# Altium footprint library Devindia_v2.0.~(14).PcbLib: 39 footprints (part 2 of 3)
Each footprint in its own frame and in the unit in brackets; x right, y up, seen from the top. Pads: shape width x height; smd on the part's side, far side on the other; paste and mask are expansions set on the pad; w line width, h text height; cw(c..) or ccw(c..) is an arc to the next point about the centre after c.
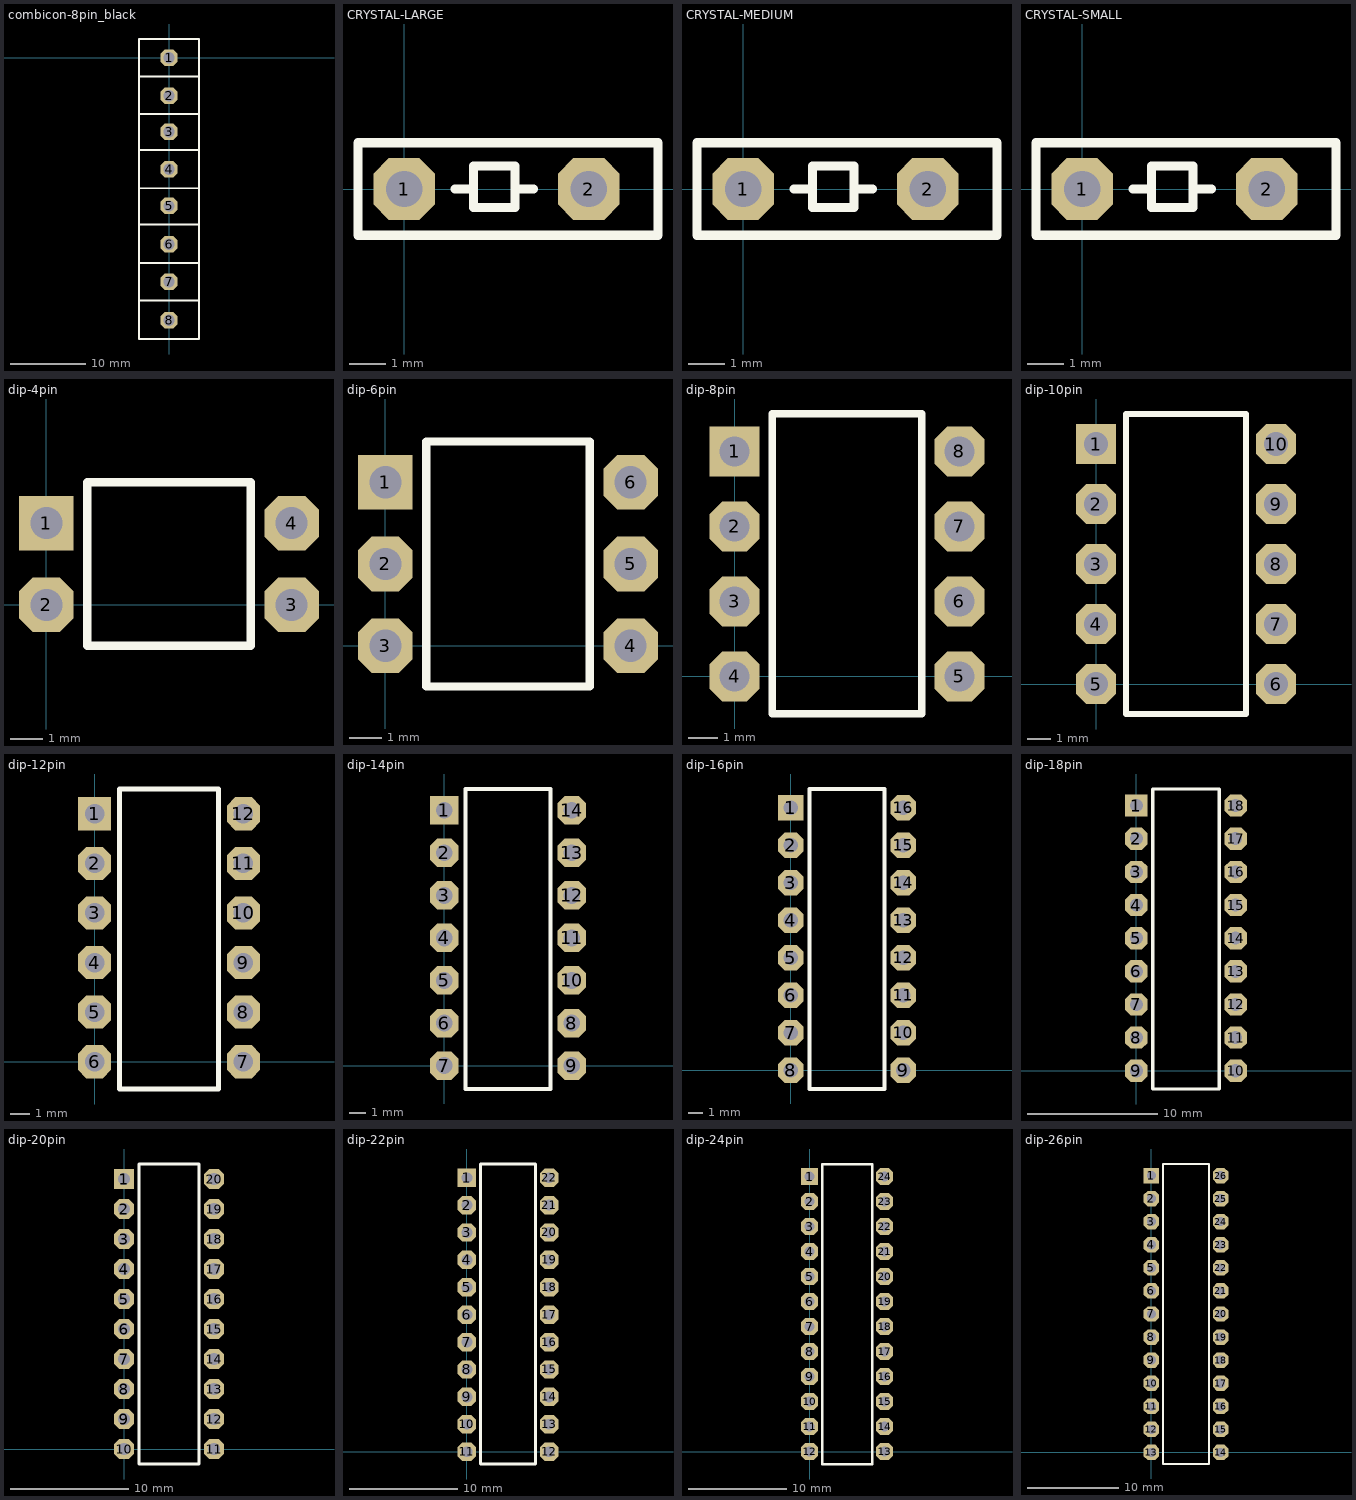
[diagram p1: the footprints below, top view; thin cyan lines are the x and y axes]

## combicon-8pin_black [mm]
pads (8):
  oct 2.2x2.2 hole 1.5: 1(0,0) 2(0,-5.08) 3(0,-9.85) 4(0,-14.875) 5(0,-19.75) 6(0,-24.875) 7(0,-29.875) 8(0,-35)
Top Overlay:
  lines w0.254: -4,-32.375 3.95,-32.375 4,-32.325 4,-27.375 ; -4,-22.25 4,-22.25 ; -4,-17.4 4,-17.4 ; -4,-12.325 4,-12.325 ; -4,-2.5 4,-2.5 ; -3.925,-27.375 4,-27.375 ; -4,-7.5 4,-7.5 ; -4,-7.5 -4,2.5 4,2.5 4,-7.5 ; -4,-7.5 -4,-27.3 -4,-37.5 4,-37.5 4,-27.375 ; 4,-27.375 4,-7.5
3D body: height 8.5, standoff 0, extent -3.937,-2.413 3.937,2.413
3D body: height 8.5, standoff 0, extent -3.937,-7.493 3.937,-2.413
3D body: height 12.4, standoff 8.5, extent -2.679,-37.537 4,2.413
3D body: height 12.9, standoff 12.4, extent -1.905,-6.731 1.88,-2.939
3D body: height 12.9, standoff 12.4, extent -1.778,-1.905 2.007,1.887
3D body: height 8.5, standoff 0, extent -3.937,-17.399 3.937,-12.319
3D body: height 8.5, standoff 0, extent -3.937,-12.319 3.937,-7.493
3D body: height 8.5, standoff 0, extent -3.937,-27.305 3.937,-22.225
3D body: height 8.5, standoff 0, extent -3.937,-22.225 3.937,-17.399
3D body: height 12.9, standoff 12.4, extent -1.853,-11.78 1.932,-7.987
3D body: height 12.9, standoff 12.4, extent -1.828,-16.755 1.957,-12.963
3D body: height 12.9, standoff 12.4, extent -1.803,-21.73 1.982,-17.938
3D body: height 12.9, standoff 12.4, extent -1.803,-26.755 1.982,-22.963
3D body: height 8.5, standoff 0, extent -3.937,-32.33 3.937,-27.25
3D body: height 8.5, standoff 0, extent -3.937,-37.405 3.937,-32.325
3D body: height 12.9, standoff 12.4, extent -1.803,-31.755 1.982,-27.963
3D body: height 12.9, standoff 12.4, extent -1.803,-36.88 1.982,-33.088

## CRYSTAL-LARGE [mm]
pads (2):
  oct 1.7x1.7 hole 1: 1(0,0) 2(5.08,0)
Top Overlay:
  lines w0.254: 1.397,0 1.905,0 ; 3.048,0 3.556,0 ; -1.27,-1.27 -1.27,1.27 6.985,1.27 6.985,-1.27 -1.27,-1.27 ; 1.905,-0.508 1.905,0.635 3.048,0.635 3.048,-0.508 1.905,-0.508
3D body: height 0.3, standoff 0, extent 3.483,-2.191 7.874,2.191
3D body: height 0.3, standoff 0, extent -2.069,-2.224 2.323,2.159
3D body: height 0.3, standoff 0, extent 0,-2.25 6.1,2.159
3D body: height 13.15, standoff 0.3, extent -1.715,-1.743 1.778,1.743
3D body: height 13.15, standoff 0.3, extent 3.873,-1.743 7.366,1.743
3D body: height 13.1, standoff 0.3, extent -0.254,-1.778 5.334,1.778

## CRYSTAL-MEDIUM [mm]
pads (2):
  oct 1.7x1.7 hole 1: 1(0,0) 2(5.08,0)
Top Overlay:
  lines w0.254: 1.397,0 1.905,0 ; 3.048,0 3.556,0 ; -1.27,-1.27 6.985,-1.27 6.985,1.27 -1.27,1.27 -1.27,-1.27 ; 1.905,-0.508 3.048,-0.508 3.048,0.635 1.905,0.635 1.905,-0.508
3D body: height 3.6, standoff 0.3, extent -0.254,-1.778 5.334,1.778
3D body: height 3.63, standoff 0.3, extent 3.873,-1.743 7.366,1.743
3D body: height 3.63, standoff 0.3, extent -1.715,-1.743 1.778,1.743
3D body: height 0.3, standoff 0, extent 0,-2.224 6.096,2.159
3D body: height 0.3, standoff 0, extent -2.069,-2.224 2.323,2.159
3D body: height 0.3, standoff 0, extent 3.483,-2.191 7.874,2.191

## CRYSTAL-SMALL [mm]
pads (2):
  oct 1.7x1.7 hole 1: 1(0,0) 2(5.08,0)
Top Overlay:
  lines w0.254: 1.397,0 1.905,0 ; 3.048,0 3.556,0 ; -1.27,-1.27 -1.27,1.27 6.985,1.27 6.985,-1.27 -1.27,-1.27 ; 1.905,-0.508 1.905,0.635 3.048,0.635 3.048,-0.508 1.905,-0.508
3D body: height 0.3, standoff 0, extent 3.429,-2.225 7.821,2.158
3D body: height 0.3, standoff 0, extent -2.069,-2.224 2.323,2.159
3D body: height 0.3, standoff 0, extent 0,-2.225 6.1,2.159
3D body: height 3.63, standoff 0.3, extent -1.715,-1.743 1.778,1.743
3D body: height 3.63, standoff 0.3, extent 3.873,-1.743 7.366,1.743
3D body: height 3.6, standoff 0.3, extent -0.254,-1.75 5.6,1.75

## dip-4pin [mm]
pads (4):
  rect 1.7x1.7 hole 1: 1(0,2.54)
  oct 1.7x1.7 hole 1: 2(0,0) 3(7.62,0) 4(7.62,2.54)
Top Overlay:
  lines w0.254: 1.27,-1.27 1.27,3.81 6.35,3.81 6.35,-1.27 1.27,-1.27
3D body: height 2.5, standoff 2, extent 1.778,-1.27 5.842,3.81
3D body: height 2.51, standoff 2.5, extent 2.286,2.032 3.284,3.028
3D body: height 1.63, standoff 1.37, extent 5.715,2.159 7.62,2.921
3D body: height 1.5, standoff 0, extent 7.493,2.159 7.747,2.921
3D body: height 1.63, standoff 1.37, extent 7.494,2.159 7.746,2.921
3D body: height 1.63, standoff 1.37, extent 5.715,-0.381 7.62,0.381
3D body: height 1.5, standoff 0, extent 7.493,-0.381 7.747,0.381
3D body: height 1.63, standoff 1.37, extent 7.494,-0.381 7.746,0.381
3D body: height 1.63, standoff 1.37, extent 0,-0.381 1.905,0.381
3D body: height 1.5, standoff 0, extent -0.127,-0.381 0.127,0.381
3D body: height 1.63, standoff 1.37, extent -0.126,-0.381 0.126,0.381
3D body: height 1.63, standoff 1.37, extent -0.126,2.159 0.126,2.921
3D body: height 1.5, standoff 0, extent -0.127,2.159 0.127,2.921
3D body: height 1.63, standoff 1.37, extent 0,2.159 1.905,2.921
3D body: height 2, standoff 1.1, extent 1.27,-1.27 6.35,3.81

## dip-6pin [mm]
pads (6):
  rect 1.7x1.7 hole 1: 1(0,5.08)
  oct 1.7x1.7 hole 1: 2(0,2.54) 3(0,0) 4(7.62,0) 5(7.62,2.54) 6(7.62,5.08)
Top Overlay:
  lines w0.254: 1.27,-1.27 6.35,-1.27 6.35,6.35 1.27,6.35 1.27,-1.27
3D body: height 1.63, standoff 1.37, extent -0.127,2.159 1.778,2.921
3D body: height 1.63, standoff 1.37, extent -0.127,4.699 1.778,5.461
3D body: height 1.63, standoff 1.37, extent -0.127,-0.381 1.778,0.381
3D body: height 1.63, standoff 1.37, extent 5.842,-0.381 7.747,0.381
3D body: height 1.63, standoff 1.37, extent 5.842,2.159 7.747,2.921
3D body: height 1.63, standoff 1.37, extent 5.842,4.699 7.747,5.461
3D body: height 1.63, standoff 1.37, extent -0.126,4.699 0.126,5.461
3D body: height 1.5, standoff 0, extent -0.127,4.699 0.127,5.461
3D body: height 1.63, standoff 1.37, extent -0.126,2.159 0.126,2.921
3D body: height 1.5, standoff 0, extent -0.127,2.159 0.127,2.921
3D body: height 1.63, standoff 1.37, extent -0.126,-0.381 0.126,0.381
3D body: height 1.5, standoff 0, extent -0.127,-0.381 0.127,0.381
3D body: height 1.63, standoff 1.37, extent 7.494,-0.381 7.746,0.381
3D body: height 1.5, standoff 0, extent 7.493,-0.381 7.747,0.381
3D body: height 1.63, standoff 1.37, extent 7.494,2.159 7.746,2.921
3D body: height 1.5, standoff 0, extent 7.493,2.159 7.747,2.921
3D body: height 1.63, standoff 1.37, extent 7.494,4.699 7.746,5.461
3D body: height 1.5, standoff 0, extent 7.493,4.699 7.747,5.461
3D body: height 2, standoff 1.1, extent 1.27,-1.27 6.35,6.35
3D body: height 2.51, standoff 2.5, extent 2.041,4.592 3.039,5.588
3D body: height 2.5, standoff 2, extent 1.778,-1.27 5.842,6.35

## dip-8pin [mm]
pads (8):
  rect 1.7x1.7 hole 1: 1(0,7.62)
  oct 1.7x1.7 hole 1: 2(0,5.08) 3(0,2.54) 4(0,0) 5(7.62,0) 6(7.62,2.54) 7(7.62,5.08) 8(7.62,7.62)
Top Overlay:
  lines w0.254: 1.27,-1.27 6.35,-1.27 6.35,8.89 1.27,8.89 1.27,-1.27
3D body: height 1.63, standoff 1.37, extent -0.127,4.699 1.778,5.461
3D body: height 1.63, standoff 1.37, extent -0.127,7.239 1.778,8.001
3D body: height 1.63, standoff 1.37, extent -0.127,2.159 1.778,2.921
3D body: height 1.63, standoff 1.37, extent -0.127,-0.381 1.778,0.381
3D body: height 1.63, standoff 1.37, extent 5.842,-0.381 7.747,0.381
3D body: height 1.63, standoff 1.37, extent 5.842,2.159 7.747,2.921
3D body: height 1.63, standoff 1.37, extent 5.842,4.699 7.747,5.461
3D body: height 1.63, standoff 1.37, extent 5.842,7.239 7.747,8.001
3D body: height 1.63, standoff 1.37, extent -0.126,7.239 0.126,8.001
3D body: height 1.5, standoff 0, extent -0.127,7.239 0.127,8.001
3D body: height 1.63, standoff 1.37, extent -0.126,4.699 0.126,5.461
3D body: height 1.5, standoff 0, extent -0.127,4.699 0.127,5.461
3D body: height 1.63, standoff 1.37, extent -0.126,2.159 0.126,2.921
3D body: height 1.5, standoff 0, extent -0.127,2.159 0.127,2.921
3D body: height 1.63, standoff 1.37, extent -0.126,-0.381 0.126,0.381
3D body: height 1.5, standoff 0, extent -0.127,-0.381 0.127,0.381
3D body: height 1.63, standoff 1.37, extent 7.494,-0.381 7.746,0.381
3D body: height 1.5, standoff 0, extent 7.493,-0.381 7.747,0.381
3D body: height 1.63, standoff 1.37, extent 7.494,2.159 7.746,2.921
3D body: height 1.5, standoff 0, extent 7.493,2.159 7.747,2.921
3D body: height 1.63, standoff 1.37, extent 7.494,4.699 7.746,5.461
3D body: height 1.5, standoff 0, extent 7.493,4.699 7.747,5.461
3D body: height 1.63, standoff 1.37, extent 7.494,7.239 7.746,8.001
3D body: height 1.5, standoff 0, extent 7.493,7.239 7.747,8.001
3D body: height 2, standoff 1.1, extent 1.27,-1.27 6.35,8.89
3D body: height 2.51, standoff 2.5, extent 2.041,7.132 3.039,8.128
3D body: height 2.5, standoff 2, extent 1.778,-1.27 5.842,8.89

## dip-10pin [mm]
pads (10):
  rect 1.7x1.7 hole 1: 1(0,10.16)
  oct 1.7x1.7 hole 1: 2(0,7.62) 3(0,5.08) 4(0,2.54) 5(0,0) 6(7.62,0) 7(7.62,2.54) 8(7.62,5.08) 9(7.62,7.62) 10(7.62,10.16)
Top Overlay:
  lines w0.254: 1.27,-1.27 6.35,-1.27 6.35,11.43 1.27,11.43 1.27,-1.27
3D body: height 1.5, standoff 0, extent 7.493,4.699 7.747,5.461
3D body: height 1.63, standoff 1.37, extent 7.494,4.699 7.746,5.461
3D body: height 1.63, standoff 1.37, extent 5.842,4.699 7.747,5.461
3D body: height 1.63, standoff 1.37, extent -0.127,7.239 1.778,8.001
3D body: height 1.63, standoff 1.37, extent -0.127,9.779 1.778,10.541
3D body: height 1.63, standoff 1.37, extent -0.127,4.699 1.778,5.461
3D body: height 1.63, standoff 1.37, extent -0.127,2.159 1.778,2.921
3D body: height 1.63, standoff 1.37, extent -0.127,-0.381 1.778,0.381
3D body: height 1.63, standoff 1.37, extent 5.842,-0.381 7.747,0.381
3D body: height 1.63, standoff 1.37, extent 5.842,2.159 7.747,2.921
3D body: height 1.63, standoff 1.37, extent 5.842,9.779 7.747,10.541
3D body: height 1.63, standoff 1.37, extent -0.126,9.779 0.126,10.541
3D body: height 1.5, standoff 0, extent -0.127,9.779 0.127,10.541
3D body: height 1.63, standoff 1.37, extent -0.126,7.239 0.126,8.001
3D body: height 1.5, standoff 0, extent -0.127,7.239 0.127,8.001
3D body: height 1.63, standoff 1.37, extent -0.126,4.699 0.126,5.461
3D body: height 1.5, standoff 0, extent -0.127,4.699 0.127,5.461
3D body: height 1.63, standoff 1.37, extent -0.126,2.159 0.126,2.921
3D body: height 1.5, standoff 0, extent -0.127,2.159 0.127,2.921
3D body: height 1.63, standoff 1.37, extent -0.126,-0.381 0.126,0.381
3D body: height 1.5, standoff 0, extent -0.127,-0.381 0.127,0.381
3D body: height 1.63, standoff 1.37, extent 7.494,-0.381 7.746,0.381
3D body: height 1.5, standoff 0, extent 7.493,-0.381 7.747,0.381
3D body: height 1.63, standoff 1.37, extent 7.494,2.159 7.746,2.921
3D body: height 1.5, standoff 0, extent 7.493,2.159 7.747,2.921
3D body: height 1.63, standoff 1.37, extent 7.494,9.779 7.746,10.541
3D body: height 1.5, standoff 0, extent 7.493,9.779 7.747,10.541
3D body: height 2, standoff 1.1, extent 1.27,-1.27 6.35,11.43
3D body: height 2.51, standoff 2.5, extent 2.041,9.672 3.039,10.668
3D body: height 2.5, standoff 2, extent 1.778,-1.27 5.842,11.43
3D body: height 1.63, standoff 1.37, extent 5.842,7.239 7.747,8.001
3D body: height 1.63, standoff 1.37, extent 7.494,7.239 7.746,8.001
3D body: height 1.5, standoff 0, extent 7.493,7.239 7.747,8.001

## dip-12pin [mm]
pads (12):
  rect 1.7x1.7 hole 1: 1(0,12.7)
  oct 1.7x1.7 hole 1: 2(0,10.16) 3(0,7.62) 4(0,5.08) 5(0,2.54) 6(0,0) 7(7.62,0) 8(7.62,2.54) 9(7.62,5.08) 10(7.62,7.62) 11(7.62,10.16) 12(7.62,12.7)
Top Overlay:
  lines w0.254: 1.27,-1.397 1.27,13.97 6.35,13.97 6.35,-1.397 1.27,-1.397
3D body: height 1.5, standoff 0, extent 7.493,4.699 7.747,5.461
3D body: height 1.63, standoff 1.37, extent 7.494,4.699 7.746,5.461
3D body: height 1.63, standoff 1.37, extent 5.842,4.699 7.747,5.461
3D body: height 2.5, standoff 2, extent 1.778,-1.27 5.842,13.97
3D body: height 2.51, standoff 2.5, extent 2.041,12.212 3.039,13.208
3D body: height 2, standoff 1.1, extent 1.27,-1.397 6.35,13.97
3D body: height 1.5, standoff 0, extent 7.493,12.319 7.747,13.081
3D body: height 1.63, standoff 1.37, extent 7.494,12.319 7.746,13.081
3D body: height 1.5, standoff 0, extent 7.493,9.779 7.747,10.541
3D body: height 1.63, standoff 1.37, extent 7.494,9.779 7.746,10.541
3D body: height 1.5, standoff 0, extent 7.493,7.239 7.747,8.001
3D body: height 1.63, standoff 1.37, extent 7.494,7.239 7.746,8.001
3D body: height 1.5, standoff 0, extent 7.493,2.159 7.747,2.921
3D body: height 1.63, standoff 1.37, extent 7.494,2.159 7.746,2.921
3D body: height 1.5, standoff 0, extent 7.493,-0.381 7.747,0.381
3D body: height 1.63, standoff 1.37, extent 7.494,-0.381 7.746,0.381
3D body: height 1.5, standoff 0, extent -0.127,-0.381 0.127,0.381
3D body: height 1.63, standoff 1.37, extent -0.126,-0.381 0.126,0.381
3D body: height 1.5, standoff 0, extent -0.127,2.159 0.127,2.921
3D body: height 1.63, standoff 1.37, extent -0.126,2.159 0.126,2.921
3D body: height 1.5, standoff 0, extent -0.127,4.699 0.127,5.461
3D body: height 1.63, standoff 1.37, extent -0.126,4.699 0.126,5.461
3D body: height 1.5, standoff 0, extent -0.127,7.239 0.127,8.001
3D body: height 1.63, standoff 1.37, extent -0.126,7.239 0.126,8.001
3D body: height 1.5, standoff 0, extent -0.127,9.779 0.127,10.541
3D body: height 1.63, standoff 1.37, extent -0.126,9.779 0.126,10.541
3D body: height 1.5, standoff 0, extent -0.127,12.319 0.127,13.081
3D body: height 1.63, standoff 1.37, extent -0.126,12.319 0.126,13.081
3D body: height 1.63, standoff 1.37, extent 5.842,12.319 7.747,13.081
3D body: height 1.63, standoff 1.37, extent 5.842,9.779 7.747,10.541
3D body: height 1.63, standoff 1.37, extent 5.842,7.239 7.747,8.001
3D body: height 1.63, standoff 1.37, extent 5.842,2.159 7.747,2.921
3D body: height 1.63, standoff 1.37, extent 5.842,-0.381 7.747,0.381
3D body: height 1.63, standoff 1.37, extent -0.127,-0.381 1.778,0.381
3D body: height 1.63, standoff 1.37, extent -0.127,2.159 1.778,2.921
3D body: height 1.63, standoff 1.37, extent -0.127,4.699 1.778,5.461
3D body: height 1.63, standoff 1.37, extent -0.127,7.239 1.778,8.001
3D body: height 1.63, standoff 1.37, extent -0.127,12.319 1.778,13.081
3D body: height 1.63, standoff 1.37, extent -0.127,9.779 1.778,10.541

## dip-14pin [mm]
pads (14):
  rect 1.7x1.7 hole 1: 1(0,15.24)
  oct 1.7x1.7 hole 1: 2(0,12.7) 3(0,10.16) 4(0,7.62) 5(0,5.08) 6(0,2.54) 7(0,0) 8(7.62,2.54) 9(7.62,0) 10(7.62,5.08) 11(7.62,7.62) 12(7.62,10.16) 13(7.62,12.7) 14(7.62,15.24)
Top Overlay:
  lines w0.254: 1.27,-1.397 6.35,-1.397 6.35,16.51 1.27,16.51 1.27,-1.397
3D body: height 1.5, standoff 0, extent 7.493,2.159 7.747,2.921
3D body: height 1.63, standoff 1.37, extent 7.494,2.159 7.746,2.921
3D body: height 1.63, standoff 1.37, extent 5.842,2.159 7.747,2.921
3D body: height 1.63, standoff 1.37, extent 7.621,14.859 7.873,15.621
3D body: height 1.5, standoff 0, extent 7.62,14.859 7.874,15.621
3D body: height 1.63, standoff 1.37, extent 5.842,14.859 7.747,15.621
3D body: height 1.63, standoff 1.37, extent 5.842,12.319 7.747,13.081
3D body: height 1.5, standoff 0, extent 7.62,12.319 7.874,13.081
3D body: height 1.63, standoff 1.37, extent 7.621,12.319 7.873,13.081
3D body: height 1.63, standoff 1.37, extent -0.127,12.319 1.778,13.081
3D body: height 1.63, standoff 1.37, extent -0.127,14.859 1.778,15.621
3D body: height 1.63, standoff 1.37, extent -0.127,9.779 1.778,10.541
3D body: height 1.63, standoff 1.37, extent -0.127,7.239 1.778,8.001
3D body: height 1.63, standoff 1.37, extent -0.127,4.699 1.778,5.461
3D body: height 1.63, standoff 1.37, extent -0.127,2.159 1.778,2.921
3D body: height 1.63, standoff 1.37, extent -0.127,-0.381 1.778,0.381
3D body: height 1.63, standoff 1.37, extent 5.842,-0.381 7.747,0.381
3D body: height 1.63, standoff 1.37, extent 5.842,4.699 7.747,5.461
3D body: height 1.63, standoff 1.37, extent 5.842,7.239 7.747,8.001
3D body: height 1.63, standoff 1.37, extent 5.842,9.779 7.747,10.541
3D body: height 1.63, standoff 1.37, extent -0.126,14.859 0.126,15.621
3D body: height 1.5, standoff 0, extent -0.127,14.859 0.127,15.621
3D body: height 1.63, standoff 1.37, extent -0.126,12.319 0.126,13.081
3D body: height 1.5, standoff 0, extent -0.127,12.319 0.127,13.081
3D body: height 1.63, standoff 1.37, extent -0.126,9.779 0.126,10.541
3D body: height 1.5, standoff 0, extent -0.127,9.779 0.127,10.541
3D body: height 1.63, standoff 1.37, extent -0.126,7.239 0.126,8.001
3D body: height 1.5, standoff 0, extent -0.127,7.239 0.127,8.001
3D body: height 1.63, standoff 1.37, extent -0.126,4.699 0.126,5.461
3D body: height 1.5, standoff 0, extent -0.127,4.699 0.127,5.461
3D body: height 1.63, standoff 1.37, extent -0.126,2.159 0.126,2.921
3D body: height 1.5, standoff 0, extent -0.127,2.159 0.127,2.921
3D body: height 1.63, standoff 1.37, extent -0.126,-0.381 0.126,0.381
3D body: height 1.5, standoff 0, extent -0.127,-0.381 0.127,0.381
3D body: height 1.63, standoff 1.37, extent 7.494,-0.381 7.746,0.381
3D body: height 1.5, standoff 0, extent 7.493,-0.381 7.747,0.381
3D body: height 1.63, standoff 1.37, extent 7.494,4.699 7.746,5.461
3D body: height 1.5, standoff 0, extent 7.493,4.699 7.747,5.461
3D body: height 1.63, standoff 1.37, extent 7.494,7.239 7.746,8.001
3D body: height 1.5, standoff 0, extent 7.493,7.239 7.747,8.001
3D body: height 1.63, standoff 1.37, extent 7.494,9.779 7.746,10.541
3D body: height 1.5, standoff 0, extent 7.493,9.779 7.747,10.541
3D body: height 2, standoff 1.1, extent 1.27,-1.27 6.35,16.51
3D body: height 2.51, standoff 2.5, extent 2.041,14.752 3.039,15.748
3D body: height 2.5, standoff 2, extent 1.778,-1.397 5.842,16.51

## dip-16pin [mm]
pads (16):
  rect 1.7x1.7 hole 1: 1(0,17.78)
  oct 1.7x1.7 hole 1: 2(0,15.24) 3(0,12.7) 4(0,10.16) 5(0,7.62) 6(0,5.08) 7(0,2.54) 8(0,0) 9(7.62,0) 10(7.62,2.54) 11(7.62,5.08) 12(7.62,7.62) 13(7.62,10.16) 14(7.62,12.7) 15(7.62,15.24) 16(7.62,17.78)
Top Overlay:
  lines w0.254: 1.27,-1.27 1.27,19.05 6.35,19.05 6.35,-1.27 1.27,-1.27
3D body: height 1.63, standoff 1.37, extent 7.621,12.319 7.873,13.081
3D body: height 1.5, standoff 0, extent 7.62,12.319 7.874,13.081
3D body: height 1.63, standoff 1.37, extent 5.842,12.319 7.747,13.081
3D body: height 2.5, standoff 2, extent 1.778,-1.27 5.842,19.05
3D body: height 2.51, standoff 2.5, extent 2.041,17.292 3.039,18.288
3D body: height 1.5, standoff 0, extent 7.493,17.399 7.747,18.161
3D body: height 1.63, standoff 1.37, extent 7.494,17.399 7.746,18.161
3D body: height 2, standoff 1.1, extent 1.27,-1.27 6.35,19.05
3D body: height 1.5, standoff 0, extent 7.493,7.239 7.747,8.001
3D body: height 1.63, standoff 1.37, extent 7.494,7.239 7.746,8.001
3D body: height 1.5, standoff 0, extent 7.493,4.699 7.747,5.461
3D body: height 1.63, standoff 1.37, extent 7.494,4.699 7.746,5.461
3D body: height 1.5, standoff 0, extent 7.493,2.159 7.747,2.921
3D body: height 1.63, standoff 1.37, extent 7.494,2.159 7.746,2.921
3D body: height 1.5, standoff 0, extent 7.493,-0.381 7.747,0.381
3D body: height 1.63, standoff 1.37, extent 7.494,-0.381 7.746,0.381
3D body: height 1.5, standoff 0, extent -0.127,-0.381 0.127,0.381
3D body: height 1.63, standoff 1.37, extent -0.126,-0.381 0.126,0.381
3D body: height 1.5, standoff 0, extent -0.127,2.159 0.127,2.921
3D body: height 1.63, standoff 1.37, extent -0.126,2.159 0.126,2.921
3D body: height 1.5, standoff 0, extent -0.127,4.699 0.127,5.461
3D body: height 1.63, standoff 1.37, extent -0.126,4.699 0.126,5.461
3D body: height 1.5, standoff 0, extent -0.127,7.239 0.127,8.001
3D body: height 1.63, standoff 1.37, extent -0.126,7.239 0.126,8.001
3D body: height 1.5, standoff 0, extent -0.127,9.779 0.127,10.541
3D body: height 1.63, standoff 1.37, extent -0.126,9.779 0.126,10.541
3D body: height 1.5, standoff 0, extent -0.127,12.319 0.127,13.081
3D body: height 1.63, standoff 1.37, extent -0.126,12.319 0.126,13.081
3D body: height 1.5, standoff 0, extent -0.127,14.859 0.127,15.621
3D body: height 1.63, standoff 1.37, extent -0.126,14.859 0.126,15.621
3D body: height 1.5, standoff 0, extent -0.127,17.399 0.127,18.161
3D body: height 1.63, standoff 1.37, extent -0.126,17.399 0.126,18.161
3D body: height 1.63, standoff 1.37, extent 5.842,7.239 7.747,8.001
3D body: height 1.63, standoff 1.37, extent 5.842,4.699 7.747,5.461
3D body: height 1.63, standoff 1.37, extent 5.842,2.159 7.747,2.921
3D body: height 1.63, standoff 1.37, extent 5.842,-0.381 7.747,0.381
3D body: height 1.63, standoff 1.37, extent -0.127,-0.381 1.778,0.381
3D body: height 1.63, standoff 1.37, extent -0.127,2.159 1.778,2.921
3D body: height 1.63, standoff 1.37, extent -0.127,4.699 1.778,5.461
3D body: height 1.63, standoff 1.37, extent -0.127,7.239 1.778,8.001
3D body: height 1.63, standoff 1.37, extent -0.127,9.779 1.778,10.541
3D body: height 1.63, standoff 1.37, extent -0.127,12.319 1.778,13.081
3D body: height 1.63, standoff 1.37, extent -0.127,17.399 1.778,18.161
3D body: height 1.63, standoff 1.37, extent -0.127,14.859 1.778,15.621
3D body: height 1.63, standoff 1.37, extent 7.621,9.779 7.873,10.541
3D body: height 1.5, standoff 0, extent 7.62,9.779 7.874,10.541
3D body: height 1.63, standoff 1.37, extent 5.842,9.779 7.747,10.541
3D body: height 1.63, standoff 1.37, extent 5.842,14.859 7.747,15.621
3D body: height 1.63, standoff 1.37, extent 5.842,17.399 7.747,18.161
3D body: height 1.5, standoff 0, extent 7.62,17.399 7.874,18.161
3D body: height 1.63, standoff 1.37, extent 7.621,17.399 7.873,18.161
3D body: height 1.5, standoff 0, extent 7.62,14.859 7.874,15.621
3D body: height 1.63, standoff 1.37, extent 7.621,14.859 7.873,15.621

## dip-18pin [mm]
pads (18):
  rect 1.7x1.7 hole 1: 1(0,20.32)
  oct 1.7x1.7 hole 1: 2(0,17.78) 3(0,15.24) 4(0,12.7) 5(0,10.16) 6(0,7.62) 7(0,5.08) 8(0,2.54) 9(0,0) 10(7.62,0) 11(7.62,2.54) 12(7.62,5.08) 13(7.62,7.62) 14(7.62,10.16) 15(7.62,12.7) 16(7.62,15.24) 17(7.62,17.78) 18(7.62,20.32)
Top Overlay:
  lines w0.254: 1.27,-1.397 6.35,-1.397 6.35,21.59 1.27,21.59 1.27,-1.397
3D body: height 1.63, standoff 1.37, extent 7.621,12.319 7.873,13.081
3D body: height 1.5, standoff 0, extent 7.62,12.319 7.874,13.081
3D body: height 1.63, standoff 1.37, extent 7.621,14.859 7.873,15.621
3D body: height 1.5, standoff 0, extent 7.62,14.859 7.874,15.621
3D body: height 1.63, standoff 1.37, extent 5.842,19.939 7.747,20.701
3D body: height 1.63, standoff 1.37, extent 5.842,17.399 7.747,18.161
3D body: height 1.63, standoff 1.37, extent 7.621,19.939 7.873,20.701
3D body: height 1.5, standoff 0, extent 7.62,19.939 7.874,20.701
3D body: height 1.63, standoff 1.37, extent 5.842,14.859 7.747,15.621
3D body: height 1.63, standoff 1.37, extent 7.621,17.399 7.873,18.161
3D body: height 1.5, standoff 0, extent 7.62,17.399 7.874,18.161
3D body: height 1.63, standoff 1.37, extent 5.842,12.319 7.747,13.081
3D body: height 1.63, standoff 1.37, extent 5.842,7.239 7.747,8.001
3D body: height 1.5, standoff 0, extent 7.62,7.239 7.874,8.001
3D body: height 1.63, standoff 1.37, extent 7.621,7.239 7.873,8.001
3D body: height 1.63, standoff 1.37, extent -0.127,17.399 1.778,18.161
3D body: height 1.63, standoff 1.37, extent -0.127,19.939 1.778,20.701
3D body: height 1.63, standoff 1.37, extent -0.127,14.859 1.778,15.621
3D body: height 1.63, standoff 1.37, extent -0.127,12.319 1.778,13.081
3D body: height 1.63, standoff 1.37, extent -0.127,9.779 1.778,10.541
3D body: height 1.63, standoff 1.37, extent -0.127,7.239 1.778,8.001
3D body: height 1.63, standoff 1.37, extent -0.127,4.699 1.778,5.461
3D body: height 1.63, standoff 1.37, extent -0.127,2.159 1.778,2.921
3D body: height 1.63, standoff 1.37, extent 5.842,-0.381 7.747,0.381
3D body: height 1.63, standoff 1.37, extent 5.842,2.159 7.747,2.921
3D body: height 1.63, standoff 1.37, extent 5.842,4.699 7.747,5.461
3D body: height 1.63, standoff 1.37, extent -0.126,19.939 0.126,20.701
3D body: height 1.5, standoff 0, extent -0.127,19.939 0.127,20.701
3D body: height 1.63, standoff 1.37, extent -0.126,17.399 0.126,18.161
3D body: height 1.5, standoff 0, extent -0.127,17.399 0.127,18.161
3D body: height 1.63, standoff 1.37, extent -0.126,14.859 0.126,15.621
3D body: height 1.5, standoff 0, extent -0.127,14.859 0.127,15.621
3D body: height 1.63, standoff 1.37, extent -0.126,12.319 0.126,13.081
3D body: height 1.5, standoff 0, extent -0.127,12.319 0.127,13.081
3D body: height 1.63, standoff 1.37, extent -0.126,9.779 0.126,10.541
3D body: height 1.5, standoff 0, extent -0.127,9.779 0.127,10.541
3D body: height 1.63, standoff 1.37, extent -0.126,7.239 0.126,8.001
3D body: height 1.5, standoff 0, extent -0.127,7.239 0.127,8.001
3D body: height 1.63, standoff 1.37, extent -0.126,4.699 0.126,5.461
3D body: height 1.5, standoff 0, extent -0.127,4.699 0.127,5.461
3D body: height 1.63, standoff 1.37, extent -0.126,2.159 0.126,2.921
3D body: height 1.5, standoff 0, extent -0.127,2.159 0.127,2.921
3D body: height 1.63, standoff 1.37, extent 7.494,-0.381 7.746,0.381
3D body: height 1.5, standoff 0, extent 7.493,-0.381 7.747,0.381
3D body: height 1.63, standoff 1.37, extent 7.494,2.159 7.746,2.921
3D body: height 1.5, standoff 0, extent 7.493,2.159 7.747,2.921
3D body: height 1.63, standoff 1.37, extent 7.494,4.699 7.746,5.461
3D body: height 1.5, standoff 0, extent 7.493,4.699 7.747,5.461
3D body: height 2, standoff 1.1, extent 1.27,-1.397 6.35,21.59
3D body: height 1.63, standoff 1.37, extent 7.494,14.859 7.746,15.621
3D body: height 1.5, standoff 0, extent 7.493,14.859 7.747,15.621
3D body: height 2.51, standoff 2.5, extent 2.041,19.832 3.039,20.828
3D body: height 2.5, standoff 2, extent 1.778,-1.397 5.842,21.59
3D body: height 1.63, standoff 1.37, extent -0.127,-0.381 1.778,0.381
3D body: height 1.63, standoff 1.37, extent -0.126,-0.381 0.126,0.381
3D body: height 1.5, standoff 0, extent -0.127,-0.381 0.127,0.381
3D body: height 1.63, standoff 1.37, extent 5.842,9.779 7.747,10.541
3D body: height 1.63, standoff 1.37, extent 7.494,9.779 7.746,10.541
3D body: height 1.5, standoff 0, extent 7.493,9.779 7.747,10.541

## dip-20pin [mm]
pads (20):
  rect 1.7x1.7 hole 1: 1(0,22.86)
  oct 1.7x1.7 hole 1: 2(0,20.32) 3(0,17.78) 4(0,15.24) 5(0,12.7) 6(0,10.16) 7(0,7.62) 8(0,5.08) 9(0,2.54) 10(0,0) 11(7.62,0) 12(7.62,2.54) 13(7.62,5.08) 14(7.62,7.62) 15(7.62,10.16) 16(7.62,12.7) 17(7.62,15.24) 18(7.62,17.78) 19(7.62,20.32) 20(7.62,22.86)
Top Overlay:
  lines w0.254: 1.27,-1.27 6.35,-1.27 6.35,24.13 1.27,24.13 1.27,-1.27
3D body: height 1.5, standoff 0, extent -0.127,4.699 0.127,5.461
3D body: height 1.63, standoff 1.37, extent -0.126,4.699 0.126,5.461
3D body: height 1.63, standoff 1.37, extent -0.127,4.699 1.778,5.461
3D body: height 1.5, standoff 0, extent 7.493,7.239 7.747,8.001
3D body: height 1.63, standoff 1.37, extent 7.494,7.239 7.746,8.001
3D body: height 1.63, standoff 1.37, extent 5.842,7.239 7.747,8.001
3D body: height 1.5, standoff 0, extent -0.127,2.159 0.127,2.921
3D body: height 1.63, standoff 1.37, extent -0.126,2.159 0.126,2.921
3D body: height 1.63, standoff 1.37, extent -0.127,2.159 1.778,2.921
3D body: height 1.63, standoff 1.37, extent 7.621,9.779 7.873,10.541
3D body: height 1.5, standoff 0, extent 7.62,9.779 7.874,10.541
3D body: height 1.63, standoff 1.37, extent 7.621,12.319 7.873,13.081
3D body: height 1.5, standoff 0, extent 7.62,12.319 7.874,13.081
3D body: height 1.63, standoff 1.37, extent 7.621,22.479 7.873,23.241
3D body: height 1.5, standoff 0, extent 7.62,22.479 7.874,23.241
3D body: height 1.63, standoff 1.37, extent 5.842,17.399 7.747,18.161
3D body: height 1.63, standoff 1.37, extent 7.621,19.939 7.873,20.701
3D body: height 1.5, standoff 0, extent 7.62,19.939 7.874,20.701
3D body: height 1.63, standoff 1.37, extent 5.842,14.859 7.747,15.621
3D body: height 1.63, standoff 1.37, extent 7.621,17.399 7.873,18.161
3D body: height 1.5, standoff 0, extent 7.62,17.399 7.874,18.161
3D body: height 1.63, standoff 1.37, extent 5.842,12.319 7.747,13.081
3D body: height 1.63, standoff 1.37, extent 7.621,14.859 7.873,15.621
3D body: height 1.5, standoff 0, extent 7.62,14.859 7.874,15.621
3D body: height 1.63, standoff 1.37, extent 5.842,9.779 7.747,10.541
3D body: height 1.63, standoff 1.37, extent 5.842,19.939 7.747,20.701
3D body: height 1.63, standoff 1.37, extent 5.842,22.479 7.747,23.241
3D body: height 1.63, standoff 1.37, extent 5.842,4.699 7.747,5.461
3D body: height 1.5, standoff 0, extent 7.62,4.699 7.874,5.461
3D body: height 1.63, standoff 1.37, extent 7.621,4.699 7.873,5.461
3D body: height 1.63, standoff 1.37, extent -0.127,19.939 1.778,20.701
3D body: height 1.63, standoff 1.37, extent -0.127,22.479 1.778,23.241
3D body: height 1.63, standoff 1.37, extent -0.127,17.399 1.778,18.161
3D body: height 1.63, standoff 1.37, extent -0.127,14.859 1.778,15.621
3D body: height 1.63, standoff 1.37, extent -0.127,12.319 1.778,13.081
3D body: height 1.63, standoff 1.37, extent -0.127,9.779 1.778,10.541
3D body: height 1.63, standoff 1.37, extent -0.127,7.239 1.778,8.001
3D body: height 1.63, standoff 1.37, extent -0.127,-0.381 1.778,0.381
3D body: height 1.63, standoff 1.37, extent 5.842,-0.381 7.747,0.381
3D body: height 1.63, standoff 1.37, extent 5.842,2.159 7.747,2.921
3D body: height 1.63, standoff 1.37, extent -0.126,22.479 0.126,23.241
3D body: height 1.5, standoff 0, extent -0.127,22.479 0.127,23.241
3D body: height 1.63, standoff 1.37, extent -0.126,19.939 0.126,20.701
3D body: height 1.5, standoff 0, extent -0.127,19.939 0.127,20.701
3D body: height 1.63, standoff 1.37, extent -0.126,17.399 0.126,18.161
3D body: height 1.5, standoff 0, extent -0.127,17.399 0.127,18.161
3D body: height 1.63, standoff 1.37, extent -0.126,14.859 0.126,15.621
3D body: height 1.5, standoff 0, extent -0.127,14.859 0.127,15.621
3D body: height 1.63, standoff 1.37, extent -0.126,12.319 0.126,13.081
3D body: height 1.5, standoff 0, extent -0.127,12.319 0.127,13.081
3D body: height 1.63, standoff 1.37, extent -0.126,9.779 0.126,10.541
3D body: height 1.5, standoff 0, extent -0.127,9.779 0.127,10.541
3D body: height 1.63, standoff 1.37, extent -0.126,7.239 0.126,8.001
3D body: height 1.5, standoff 0, extent -0.127,7.239 0.127,8.001
3D body: height 1.63, standoff 1.37, extent -0.126,-0.381 0.126,0.381
3D body: height 1.5, standoff 0, extent -0.127,-0.381 0.127,0.381
3D body: height 1.63, standoff 1.37, extent 7.494,-0.381 7.746,0.381
3D body: height 1.5, standoff 0, extent 7.493,-0.381 7.747,0.381
3D body: height 1.63, standoff 1.37, extent 7.494,2.159 7.746,2.921
3D body: height 1.5, standoff 0, extent 7.493,2.159 7.747,2.921
3D body: height 2, standoff 1.1, extent 1.27,-1.27 6.35,24.13
3D body: height 1.63, standoff 1.37, extent 7.494,12.319 7.746,13.081
3D body: height 1.5, standoff 0, extent 7.493,12.319 7.747,13.081
3D body: height 2.51, standoff 2.5, extent 2.041,22.372 3.039,23.368
3D body: height 2.5, standoff 2, extent 1.778,-1.27 5.842,24.13

## dip-22pin [mm]
pads (22):
  rect 1.7x1.7 hole 1: 1(0,25.4)
  oct 1.7x1.7 hole 1: 2(0,22.86) 3(0,20.32) 4(0,17.78) 5(0,15.24) 6(0,12.7) 7(0,10.16) 8(0,7.62) 9(0,5.08) 10(0,2.54) 11(0,0) 12(7.62,0) 13(7.62,2.54) 14(7.62,5.08) 15(7.62,7.62) 16(7.62,10.16) 17(7.62,12.7) 18(7.62,15.24) 19(7.62,17.78) 20(7.62,20.32) 21(7.62,22.86) 22(7.62,25.4)
Top Overlay:
  lines w0.254: 1.27,-1.143 1.27,26.67 6.35,26.67 6.35,-1.143 1.27,-1.143
3D body: height 2.5, standoff 2, extent 1.778,-1.143 5.842,26.67
3D body: height 2.51, standoff 2.5, extent 2.041,24.912 3.039,25.908
3D body: height 1.5, standoff 0, extent 7.493,9.779 7.747,10.541
3D body: height 1.63, standoff 1.37, extent 7.494,9.779 7.746,10.541
3D body: height 2, standoff 1.1, extent 1.27,-1.143 6.35,26.67
3D body: height 1.5, standoff 0, extent 7.493,-0.381 7.747,0.381
3D body: height 1.63, standoff 1.37, extent 7.494,-0.381 7.746,0.381
3D body: height 1.5, standoff 0, extent -0.127,-0.381 0.127,0.381
3D body: height 1.63, standoff 1.37, extent -0.126,-0.381 0.126,0.381
3D body: height 1.5, standoff 0, extent -0.127,2.159 0.127,2.921
3D body: height 1.63, standoff 1.37, extent -0.126,2.159 0.126,2.921
3D body: height 1.5, standoff 0, extent -0.127,7.239 0.127,8.001
3D body: height 1.63, standoff 1.37, extent -0.126,7.239 0.126,8.001
3D body: height 1.5, standoff 0, extent -0.127,9.779 0.127,10.541
3D body: height 1.63, standoff 1.37, extent -0.126,9.779 0.126,10.541
3D body: height 1.5, standoff 0, extent -0.127,12.319 0.127,13.081
3D body: height 1.63, standoff 1.37, extent -0.126,12.319 0.126,13.081
3D body: height 1.5, standoff 0, extent -0.127,14.859 0.127,15.621
3D body: height 1.63, standoff 1.37, extent -0.126,14.859 0.126,15.621
3D body: height 1.5, standoff 0, extent -0.127,17.399 0.127,18.161
3D body: height 1.63, standoff 1.37, extent -0.126,17.399 0.126,18.161
3D body: height 1.5, standoff 0, extent -0.127,19.939 0.127,20.701
3D body: height 1.63, standoff 1.37, extent -0.126,19.939 0.126,20.701
3D body: height 1.5, standoff 0, extent -0.127,22.479 0.127,23.241
3D body: height 1.63, standoff 1.37, extent -0.126,22.479 0.126,23.241
3D body: height 1.5, standoff 0, extent -0.127,25.019 0.127,25.781
3D body: height 1.63, standoff 1.37, extent -0.126,25.019 0.126,25.781
3D body: height 1.63, standoff 1.37, extent 5.842,-0.381 7.747,0.381
3D body: height 1.63, standoff 1.37, extent -0.127,-0.381 1.778,0.381
3D body: height 1.63, standoff 1.37, extent -0.127,2.159 1.778,2.921
3D body: height 1.63, standoff 1.37, extent -0.127,7.239 1.778,8.001
3D body: height 1.63, standoff 1.37, extent -0.127,9.779 1.778,10.541
3D body: height 1.63, standoff 1.37, extent -0.127,12.319 1.778,13.081
3D body: height 1.63, standoff 1.37, extent -0.127,14.859 1.778,15.621
3D body: height 1.63, standoff 1.37, extent -0.127,17.399 1.778,18.161
3D body: height 1.63, standoff 1.37, extent -0.127,19.939 1.778,20.701
3D body: height 1.63, standoff 1.37, extent -0.127,25.019 1.778,25.781
3D body: height 1.63, standoff 1.37, extent -0.127,22.479 1.778,23.241
3D body: height 1.63, standoff 1.37, extent 7.621,2.159 7.873,2.921
3D body: height 1.5, standoff 0, extent 7.62,2.159 7.874,2.921
3D body: height 1.63, standoff 1.37, extent 5.842,2.159 7.747,2.921
3D body: height 1.63, standoff 1.37, extent 5.842,25.019 7.747,25.781
3D body: height 1.63, standoff 1.37, extent 5.842,22.479 7.747,23.241
3D body: height 1.63, standoff 1.37, extent 5.842,19.939 7.747,20.701
3D body: height 1.5, standoff 0, extent 7.62,25.019 7.874,25.781
3D body: height 1.63, standoff 1.37, extent 7.621,25.019 7.873,25.781
3D body: height 1.63, standoff 1.37, extent 5.842,17.399 7.747,18.161
3D body: height 1.5, standoff 0, extent 7.62,22.479 7.874,23.241
3D body: height 1.63, standoff 1.37, extent 7.621,22.479 7.873,23.241
3D body: height 1.63, standoff 1.37, extent 5.842,7.239 7.747,8.001
3D body: height 1.5, standoff 0, extent 7.62,12.319 7.874,13.081
3D body: height 1.63, standoff 1.37, extent 7.621,12.319 7.873,13.081
3D body: height 1.63, standoff 1.37, extent 5.842,9.779 7.747,10.541
3D body: height 1.5, standoff 0, extent 7.62,14.859 7.874,15.621
3D body: height 1.63, standoff 1.37, extent 7.621,14.859 7.873,15.621
3D body: height 1.63, standoff 1.37, extent 5.842,12.319 7.747,13.081
3D body: height 1.5, standoff 0, extent 7.62,17.399 7.874,18.161
3D body: height 1.63, standoff 1.37, extent 7.621,17.399 7.873,18.161
3D body: height 1.63, standoff 1.37, extent 5.842,14.859 7.747,15.621
3D body: height 1.5, standoff 0, extent 7.62,19.939 7.874,20.701
3D body: height 1.63, standoff 1.37, extent 7.621,19.939 7.873,20.701
3D body: height 1.5, standoff 0, extent 7.62,9.779 7.874,10.541
3D body: height 1.63, standoff 1.37, extent 7.621,9.779 7.873,10.541
3D body: height 1.5, standoff 0, extent 7.62,7.239 7.874,8.001
3D body: height 1.63, standoff 1.37, extent 7.621,7.239 7.873,8.001
3D body: height 1.63, standoff 1.37, extent -0.127,4.699 1.778,5.461
3D body: height 1.63, standoff 1.37, extent -0.126,4.699 0.126,5.461
3D body: height 1.5, standoff 0, extent -0.127,4.699 0.127,5.461
3D body: height 1.63, standoff 1.37, extent 5.842,4.699 7.747,5.461
3D body: height 1.63, standoff 1.37, extent 7.494,4.699 7.746,5.461
3D body: height 1.5, standoff 0, extent 7.493,4.699 7.747,5.461

## dip-24pin [mm]
pads (24):
  rect 1.7x1.7 hole 1: 1(0,27.94)
  oct 1.7x1.7 hole 1: 2(0,25.4) 3(0,22.86) 4(0,20.32) 5(0,17.78) 6(0,15.24) 7(0,12.7) 8(0,10.16) 9(0,7.62) 10(0,5.08) 11(0,2.54) 12(0,0) 13(7.62,0) 14(7.62,2.54) 15(7.62,5.08) 16(7.62,7.62) 17(7.62,10.16) 18(7.62,12.7) 19(7.62,15.24) 20(7.62,17.78) 21(7.62,20.32) 22(7.62,22.86) 23(7.62,25.4) 24(7.62,27.94)
Top Overlay:
  lines w0.254: 1.27,-1.27 6.35,-1.27 6.35,29.21 1.27,29.21 1.27,-1.27
3D body: height 1.63, standoff 1.37, extent 7.621,4.699 7.873,5.461
3D body: height 1.5, standoff 0, extent 7.62,4.699 7.874,5.461
3D body: height 1.63, standoff 1.37, extent 7.621,7.239 7.873,8.001
3D body: height 1.5, standoff 0, extent 7.62,7.239 7.874,8.001
3D body: height 1.63, standoff 1.37, extent 5.842,2.159 7.747,2.921
3D body: height 1.63, standoff 1.37, extent 7.621,17.399 7.873,18.161
3D body: height 1.5, standoff 0, extent 7.62,17.399 7.874,18.161
3D body: height 1.63, standoff 1.37, extent 5.842,12.319 7.747,13.081
3D body: height 1.63, standoff 1.37, extent 7.621,14.859 7.873,15.621
3D body: height 1.5, standoff 0, extent 7.62,14.859 7.874,15.621
3D body: height 1.63, standoff 1.37, extent 5.842,9.779 7.747,10.541
3D body: height 1.63, standoff 1.37, extent 7.621,12.319 7.873,13.081
3D body: height 1.5, standoff 0, extent 7.62,12.319 7.874,13.081
3D body: height 1.63, standoff 1.37, extent 5.842,7.239 7.747,8.001
3D body: height 1.63, standoff 1.37, extent 7.621,9.779 7.873,10.541
3D body: height 1.5, standoff 0, extent 7.62,9.779 7.874,10.541
3D body: height 1.63, standoff 1.37, extent 5.842,4.699 7.747,5.461
3D body: height 1.63, standoff 1.37, extent 7.621,19.939 7.873,20.701
3D body: height 1.5, standoff 0, extent 7.62,19.939 7.874,20.701
3D body: height 1.63, standoff 1.37, extent 5.842,14.859 7.747,15.621
3D body: height 1.63, standoff 1.37, extent 7.621,22.479 7.873,23.241
3D body: height 1.5, standoff 0, extent 7.62,22.479 7.874,23.241
3D body: height 1.63, standoff 1.37, extent 5.842,17.399 7.747,18.161
3D body: height 1.63, standoff 1.37, extent 7.621,25.019 7.873,25.781
3D body: height 1.5, standoff 0, extent 7.62,25.019 7.874,25.781
3D body: height 1.63, standoff 1.37, extent 5.842,19.939 7.747,20.701
3D body: height 1.63, standoff 1.37, extent 7.621,27.559 7.873,28.321
3D body: height 1.5, standoff 0, extent 7.62,27.559 7.874,28.321
3D body: height 1.63, standoff 1.37, extent 5.842,22.479 7.747,23.241
3D body: height 1.63, standoff 1.37, extent 5.842,25.019 7.747,25.781
3D body: height 1.63, standoff 1.37, extent 5.842,27.559 7.747,28.321
3D body: height 1.63, standoff 1.37, extent 5.842,-0.381 7.747,0.381
3D body: height 1.5, standoff 0, extent 7.62,-0.381 7.874,0.381
3D body: height 1.63, standoff 1.37, extent 7.621,-0.381 7.873,0.381
3D body: height 1.63, standoff 1.37, extent -0.127,25.019 1.778,25.781
3D body: height 1.63, standoff 1.37, extent -0.127,27.559 1.778,28.321
3D body: height 1.63, standoff 1.37, extent -0.127,22.479 1.778,23.241
3D body: height 1.63, standoff 1.37, extent -0.127,19.939 1.778,20.701
3D body: height 1.63, standoff 1.37, extent -0.127,17.399 1.778,18.161
3D body: height 1.63, standoff 1.37, extent -0.127,14.859 1.778,15.621
3D body: height 1.63, standoff 1.37, extent -0.127,12.319 1.778,13.081
3D body: height 1.63, standoff 1.37, extent -0.127,9.779 1.778,10.541
3D body: height 1.63, standoff 1.37, extent -0.127,7.239 1.778,8.001
3D body: height 1.63, standoff 1.37, extent -0.127,4.699 1.778,5.461
3D body: height 1.63, standoff 1.37, extent -0.127,2.159 1.778,2.921
3D body: height 1.63, standoff 1.37, extent -0.127,-0.381 1.778,0.381
3D body: height 1.63, standoff 1.37, extent -0.126,27.559 0.126,28.321
3D body: height 1.5, standoff 0, extent -0.127,27.559 0.127,28.321
3D body: height 1.63, standoff 1.37, extent -0.126,25.019 0.126,25.781
3D body: height 1.5, standoff 0, extent -0.127,25.019 0.127,25.781
3D body: height 1.63, standoff 1.37, extent -0.126,22.479 0.126,23.241
3D body: height 1.5, standoff 0, extent -0.127,22.479 0.127,23.241
3D body: height 1.63, standoff 1.37, extent -0.126,19.939 0.126,20.701
3D body: height 1.5, standoff 0, extent -0.127,19.939 0.127,20.701
3D body: height 1.63, standoff 1.37, extent -0.126,17.399 0.126,18.161
3D body: height 1.5, standoff 0, extent -0.127,17.399 0.127,18.161
3D body: height 1.63, standoff 1.37, extent -0.126,14.859 0.126,15.621
3D body: height 1.5, standoff 0, extent -0.127,14.859 0.127,15.621
3D body: height 1.63, standoff 1.37, extent -0.126,12.319 0.126,13.081
3D body: height 1.5, standoff 0, extent -0.127,12.319 0.127,13.081
3D body: height 1.63, standoff 1.37, extent -0.126,9.779 0.126,10.541
3D body: height 1.5, standoff 0, extent -0.127,9.779 0.127,10.541
3D body: height 1.63, standoff 1.37, extent -0.126,7.112 0.126,7.874
3D body: height 1.5, standoff 0, extent -0.127,7.112 0.127,7.874
3D body: height 1.63, standoff 1.37, extent -0.126,4.699 0.126,5.461
3D body: height 1.5, standoff 0, extent -0.127,4.699 0.127,5.461
3D body: height 1.63, standoff 1.37, extent -0.126,2.159 0.126,2.921
3D body: height 1.5, standoff 0, extent -0.127,2.159 0.127,2.921
3D body: height 1.63, standoff 1.37, extent -0.126,-0.381 0.126,0.381
3D body: height 1.5, standoff 0, extent -0.127,-0.381 0.127,0.381
3D body: height 2, standoff 1.1, extent 1.27,-1.27 6.35,29.21
3D body: height 1.63, standoff 1.37, extent 7.494,7.239 7.746,8.001
3D body: height 1.5, standoff 0, extent 7.493,7.239 7.747,8.001
3D body: height 2.51, standoff 2.5, extent 2.041,27.452 3.039,28.448
3D body: height 2.5, standoff 2, extent 1.778,-1.27 5.842,29.21

## dip-26pin [mm]
pads (26):
  rect 1.7x1.7 hole 1: 1(0,30.48)
  oct 1.7x1.7 hole 1: 2(0,27.94) 3(0,25.4) 4(0,22.86) 5(0,20.32) 6(0,17.78) 7(0,15.24) 8(0,12.7) 9(0,10.16) 10(0,7.62) 11(0,5.08) 12(0,2.54) 13(0,0) 14(7.62,0) 15(7.62,2.54) 16(7.62,5.08) 17(7.62,7.62) 18(7.62,10.16) 19(7.62,12.7) 20(7.62,15.24) 21(7.62,17.78) 22(7.62,20.32) 23(7.62,22.86) 24(7.62,25.4) 25(7.62,27.94) 26(7.62,30.48)
Top Overlay:
  lines w0.254: 1.27,-1.27 6.35,-1.27 6.35,31.75 1.27,31.75 1.27,-1.27
3D body: height 1.63, standoff 1.37, extent 7.621,2.159 7.873,2.921
3D body: height 1.5, standoff 0, extent 7.62,2.159 7.874,2.921
3D body: height 1.63, standoff 1.37, extent 7.621,4.699 7.873,5.461
3D body: height 1.5, standoff 0, extent 7.62,4.699 7.874,5.461
3D body: height 1.63, standoff 1.37, extent 5.842,-0.381 7.747,0.381
3D body: height 1.63, standoff 1.37, extent 7.621,14.859 7.873,15.621
3D body: height 1.5, standoff 0, extent 7.62,14.859 7.874,15.621
3D body: height 1.63, standoff 1.37, extent 5.842,9.779 7.747,10.541
3D body: height 1.63, standoff 1.37, extent 7.621,12.319 7.873,13.081
3D body: height 1.5, standoff 0, extent 7.62,12.319 7.874,13.081
3D body: height 1.63, standoff 1.37, extent 5.842,7.239 7.747,8.001
3D body: height 1.63, standoff 1.37, extent 7.621,9.779 7.873,10.541
3D body: height 1.5, standoff 0, extent 7.62,9.779 7.874,10.541
3D body: height 1.63, standoff 1.37, extent 5.842,4.699 7.747,5.461
3D body: height 1.63, standoff 1.37, extent 7.621,7.239 7.873,8.001
3D body: height 1.5, standoff 0, extent 7.62,7.239 7.874,8.001
3D body: height 1.63, standoff 1.37, extent 5.842,2.159 7.747,2.921
3D body: height 1.63, standoff 1.37, extent 7.621,17.399 7.873,18.161
3D body: height 1.5, standoff 0, extent 7.62,17.399 7.874,18.161
3D body: height 1.63, standoff 1.37, extent 5.842,12.319 7.747,13.081
3D body: height 1.63, standoff 1.37, extent 7.621,19.939 7.873,20.701
3D body: height 1.5, standoff 0, extent 7.62,19.939 7.874,20.701
3D body: height 1.63, standoff 1.37, extent 5.842,14.859 7.747,15.621
3D body: height 1.63, standoff 1.37, extent 7.621,22.479 7.873,23.241
3D body: height 1.5, standoff 0, extent 7.62,22.479 7.874,23.241
3D body: height 1.63, standoff 1.37, extent 5.842,17.399 7.747,18.161
3D body: height 1.63, standoff 1.37, extent 7.621,25.019 7.873,25.781
3D body: height 1.5, standoff 0, extent 7.62,25.019 7.874,25.781
3D body: height 1.63, standoff 1.37, extent 5.842,19.939 7.747,20.701
3D body: height 1.63, standoff 1.37, extent 7.621,27.559 7.873,28.321
3D body: height 1.5, standoff 0, extent 7.62,27.559 7.874,28.321
3D body: height 1.63, standoff 1.37, extent 5.842,22.479 7.747,23.241
3D body: height 1.63, standoff 1.37, extent 7.621,30.099 7.873,30.861
3D body: height 1.5, standoff 0, extent 7.62,30.099 7.874,30.861
3D body: height 1.63, standoff 1.37, extent 5.842,25.019 7.747,25.781
3D body: height 1.63, standoff 1.37, extent 5.842,27.559 7.747,28.321
3D body: height 1.63, standoff 1.37, extent 5.842,30.099 7.747,30.861
3D body: height 1.63, standoff 1.37, extent -0.127,-0.381 1.778,0.381
3D body: height 1.5, standoff 0, extent -0.254,-0.381 0,0.381
3D body: height 1.63, standoff 1.37, extent -0.253,-0.381 -0.001,0.381
3D body: height 1.63, standoff 1.37, extent -0.127,27.559 1.778,28.321
3D body: height 1.63, standoff 1.37, extent -0.127,30.099 1.778,30.861
3D body: height 1.63, standoff 1.37, extent -0.127,25.019 1.778,25.781
3D body: height 1.63, standoff 1.37, extent -0.127,22.479 1.778,23.241
3D body: height 1.63, standoff 1.37, extent -0.127,19.939 1.778,20.701
3D body: height 1.63, standoff 1.37, extent -0.127,17.399 1.778,18.161
3D body: height 1.63, standoff 1.37, extent -0.127,14.859 1.778,15.621
3D body: height 1.63, standoff 1.37, extent -0.127,12.319 1.778,13.081
3D body: height 1.63, standoff 1.37, extent -0.127,9.779 1.778,10.541
3D body: height 1.63, standoff 1.37, extent -0.127,7.239 1.778,8.001
3D body: height 1.63, standoff 1.37, extent -0.127,4.699 1.778,5.461
3D body: height 1.63, standoff 1.37, extent -0.127,2.159 1.778,2.921
3D body: height 1.63, standoff 1.37, extent -0.126,30.099 0.126,30.861
3D body: height 1.5, standoff 0, extent -0.127,30.099 0.127,30.861
3D body: height 1.63, standoff 1.37, extent -0.126,27.559 0.126,28.321
3D body: height 1.5, standoff 0, extent -0.127,27.559 0.127,28.321
3D body: height 1.63, standoff 1.37, extent -0.126,25.019 0.126,25.781
3D body: height 1.5, standoff 0, extent -0.127,25.019 0.127,25.781
3D body: height 1.63, standoff 1.37, extent -0.126,22.479 0.126,23.241
3D body: height 1.5, standoff 0, extent -0.127,22.479 0.127,23.241
3D body: height 1.63, standoff 1.37, extent -0.126,19.939 0.126,20.701
3D body: height 1.5, standoff 0, extent -0.127,19.939 0.127,20.701
3D body: height 1.63, standoff 1.37, extent -0.126,17.399 0.126,18.161
3D body: height 1.5, standoff 0, extent -0.127,17.399 0.127,18.161
3D body: height 1.63, standoff 1.37, extent -0.126,14.859 0.126,15.621
3D body: height 1.5, standoff 0, extent -0.127,14.859 0.127,15.621
3D body: height 1.63, standoff 1.37, extent -0.126,12.319 0.126,13.081
3D body: height 1.5, standoff 0, extent -0.127,12.319 0.127,13.081
3D body: height 1.63, standoff 1.37, extent -0.126,9.652 0.126,10.414
3D body: height 1.5, standoff 0, extent -0.127,9.652 0.127,10.414
3D body: height 1.63, standoff 1.37, extent -0.126,7.239 0.126,8.001
3D body: height 1.5, standoff 0, extent -0.127,7.239 0.127,8.001
3D body: height 1.63, standoff 1.37, extent -0.126,4.699 0.126,5.461
3D body: height 1.5, standoff 0, extent -0.127,4.699 0.127,5.461
3D body: height 1.63, standoff 1.37, extent -0.126,2.159 0.126,2.921
3D body: height 1.5, standoff 0, extent -0.127,2.159 0.127,2.921
3D body: height 2, standoff 1.1, extent 1.27,-1.27 6.35,31.75
3D body: height 1.63, standoff 1.37, extent 7.494,4.699 7.746,5.461
3D body: height 1.5, standoff 0, extent 7.493,4.699 7.747,5.461
3D body: height 2.51, standoff 2.5, extent 2.041,29.992 3.039,30.988
3D body: height 2.5, standoff 2, extent 1.778,-1.27 5.842,31.75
